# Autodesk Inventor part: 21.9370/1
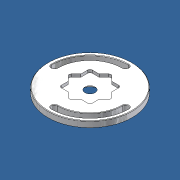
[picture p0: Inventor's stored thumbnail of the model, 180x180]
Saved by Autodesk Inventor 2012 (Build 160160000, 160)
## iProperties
Created: 2013-05
Part Number: 21.9370/1
Material: Aluminum-6061
Document SubType Name: Modeling
Designer: Admin
Density: 2.71 g/cm^3
Mass: 83.39 g
Surface Area: 148.115 cm^2
Volume: 30.7712 cm^3
Description: MILL TO 21.9370/1
Stock Number: 21.9525  1/4" ALUMINUM
Vendor: F
FINISH: ETCH & CLEAR ANODIZE
Author: Admin
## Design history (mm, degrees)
sketch "Sketch1"
  geometry: L1 (-22.5, 22.5)-(22.5, 22.5); L2 (22.5, 22.5)-(22.5, -22.5); L3 (22.5, -22.5)-(-22.5, -22.5); L4 (-22.5, -22.5)-(-22.5, 22.5); L5 (0, 0)-(-45, 0); L6 (0, 0)-(0, 45); L7 (0, 69.541)-(0, -69.541) reference; A1 r 45 centre (0, 0) between (-45, 0) and (0, 45); A2 r 3.15 centre (0, 38) between (0, 34.85) and (0, 41.15); A3 r 41.15 centre (0, 0) between (0, 41.15) and (-41.15, 0); A4 r 34.85 centre (0, 0) between (0, 34.85) and (-34.85, 0); A5 r 3.15 centre (-38, 0) between (-41.15, 0) and (-34.85, 0); A6 r 3.15 centre (0, -38) between (0, -34.85) and (0, -41.15); A7 r 34.85 centre (0, 0) between (0, -34.85) and (34.85, 0); A8 r 41.15 centre (0, 0) between (0, -41.15) and (41.15, 0); A9 r 3.15 centre (38, 0) between (41.15, 0) and (34.85, 0); 3 further points
  constraints: 18 point on circle, 12 end point, 9 centre point, 6 point on line, 4 coincident, 2 midpoint, 2 parallel, 1 horizontal, 1 horizontal alignment, 1 perpendicular, 1 tangent, 1 vertical alignment, 25 other
  dimensions: "d0" = 90 diameter of A1; "d1" = 45 distance of L1.start L1.end; "d2" = 45 distance of L1.end L2.end; "d3" = 90 deg angle of L7 L5; "d4" = 0 distance between parallel lines of L6 L7; "d7" = 6.3 diameter of A2; "d8" = 7 distance of L6.end A2.centre; "d29" = 360 deg dimension on point (0, 0) A2.centre (derived)
extrude "Extrusion1" new body sketch "Sketch1" distance "d13" = 6.35; taper "d14" = 0 deg
sketch "Sketch2"
  geometry: L1 (16.6, 16.6)-(-16.6, 16.6); L2 (-16.6, 16.6)-(-16.6, -16.6); L3 (-16.6, -16.6)-(16.6, -16.6); L4 (16.6, -16.6)-(16.6, 16.6); A1 r 41.15 centre (0, 0) between (0, 41.15) and (-41.15, 0) reference; 2 further points
  constraints: 8 end point, 2 midpoint, 2 parallel, 1 horizontal, 1 horizontal alignment, 1 perpendicular, 1 vertical alignment
  dimensions: "d15" = 33.2 distance of L1.start L1.end; "d16" = 33.2 distance of L1.end L2.end
extrude "Extrusion2" cut sketch "Sketch2" distance "d17" = 3; taper "d18" = 0 deg
fillet "Fillet1" dims "d19" = 2.38125
sketch "Sketch3"
  geometry: C1 r 45 at (0, 0) reference; 1 further point
  constraints: 1 coincident
hole "Hole1" sketch "Sketch3" at (0, 0) diameter "d20" = 8.5; stored, may be unused: countersink angle "d24" = 90 deg, drill point angle "d26" = 118 deg; dims "d21" = 6, "d22" = 17.5, "d23" = 2, "d25" = 8
sketch "Sketch4"
  geometry: L1 (-14.219, 16.6)-(14.219, 16.6) reference; L2 (-23.476, 0)-(0, 23.476); L3 (0, 23.476)-(23.476, 0); L4 (23.476, 0)-(0, -23.476); L5 (0, -23.476)-(-23.476, 0); A1 r 34.85 centre (0, 0) between (0, 34.85) and (-34.85, 0) reference
  constraints: 8 end point, 4 perpendicular
  dimensions: "d31" = 45 deg angle of L2 L1; "d32" = 33.2 distance of L2.start L2.end; "d33" = 16.6 distance from line of A1.centre L5 (= 0.5 x d32); "d34" = 16.6 distance from line of A1.centre L4 (= d33)
extrude "Extrusion3" cut sketch "Sketch4" distance "d35" = 3; taper "d36" = 0 deg
fillet "Fillet2" dims "d37" = 2.38125
chamfer "Chamfer1" distance "d38" = 0.508; stored, may be unused: second distance "d39" = 2, angle "d40" = 45 deg
body "Solid1"
